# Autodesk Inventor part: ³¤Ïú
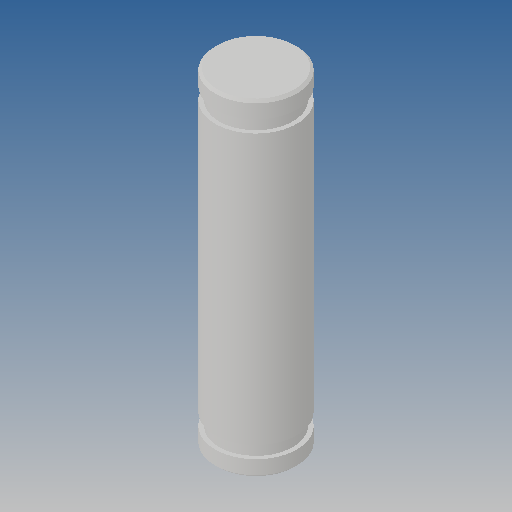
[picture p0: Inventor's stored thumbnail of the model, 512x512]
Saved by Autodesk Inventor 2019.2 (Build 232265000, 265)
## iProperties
Created: 2013-07
Part Number: ³¤Ïú
Material: Ogólny
Document SubType Name: Modeling
Designer: CADENGINEERING4
Density: 1 g/cm^3
Appearance: Domyślna
Author: CADENGINEERING4
Revision Number: ÈÎºÎ
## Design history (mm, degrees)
feature "CALC80-³¤Ïú.bak-2-solid1"
node "Bryła1"
